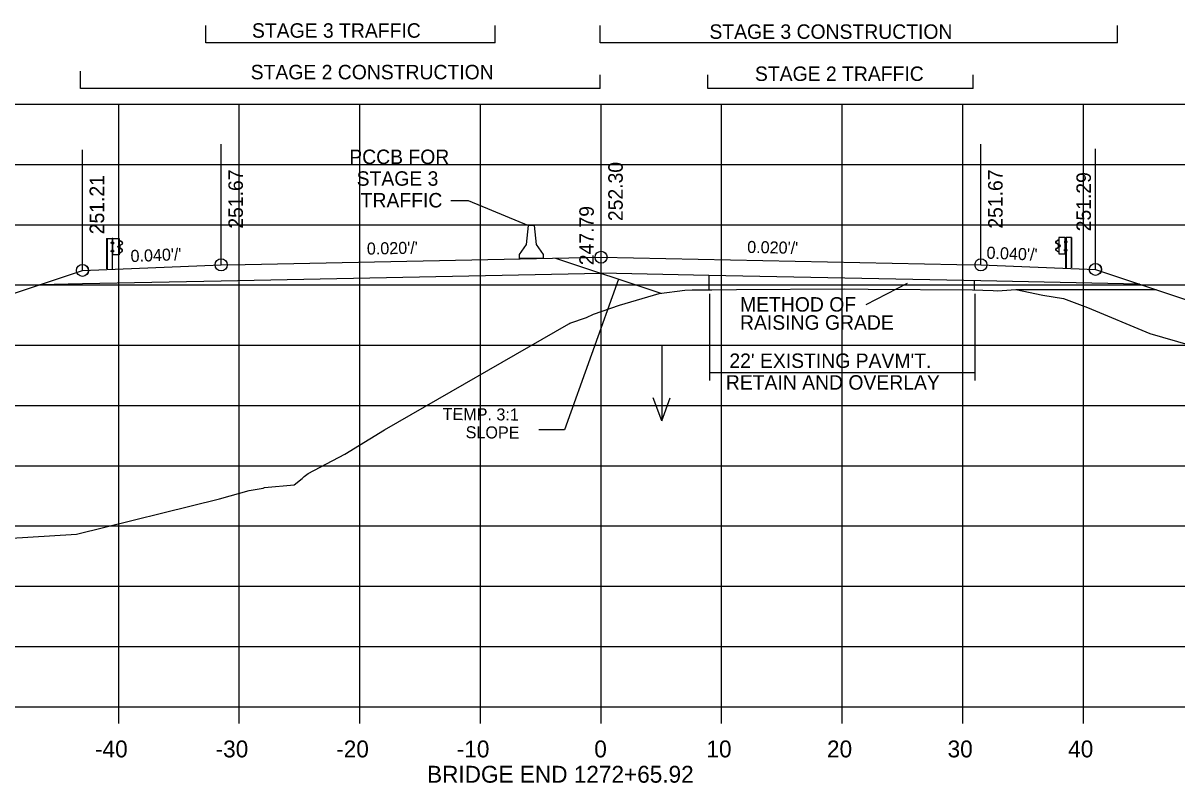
# Model space of a CAD drawing. Extents: x 1342547 to 1344156, y -1532351 to -1517216.
# Drawn here: x 1342654.9 to 1342750.6, y -1523508.6 to -1523445.5 of the extents above; entities that cross this region are included whole.
import ezdxf

# ---------------------------------------------------------------- set-up
doc = ezdxf.new("R2010")
doc.units = 0
for name, color, linetype in [('1', 7, 'Continuous'), ('R_Alt Surface', 7, 'Continuous'), ('R_Axis', 7, 'Continuous'), ('R_Axis Annot', 7, 'Continuous'), ('R_Draft', 7, 'Continuous'), ('R_Exist Surface', 7, 'Continuous'), ('R_Fin Surface', 7, 'Continuous'), ('R_Grid', 7, 'Continuous'), ('R_MOT', 7, 'Continuous'), ('R_No Plot', 7, 'Continuous'), ('R_Water', 7, 'Continuous'), ('R_Xsect Elev', 7, 'Continuous'), ('R_Xsect Slope', 7, 'Continuous')]:
    doc.layers.add(name, color=color, linetype=linetype)

msp = doc.modelspace()

# ---------------------------------------------------------------- linework, layer by layer
at = {"layer": '1'}
msp.add_lwpolyline([(1342743.866, -1523465.965), (1342803.434, -1523485.821)], dxfattribs=at)
at = {"layer": 'R_Alt Surface'}
msp.add_line((1342711.81, -1523466.467), (1342702.865, -1523466.288), dxfattribs=at)
for points in [[(1342659.865, -1523467.148), (1342671.365, -1523466.918), (1342702.865, -1523466.288)], [(1342747.514, -1523467.181), (1342734.365, -1523466.918), (1342711.81, -1523466.467)], [(1342656.338, -1523467.219), (1342659.865, -1523467.148)]]:
    msp.add_lwpolyline(points, dxfattribs=at)
at = {"layer": 'R_Axis'}
for p, q in [((1342562.865, -1523502.255), (1342842.865, -1523502.255)), ((1342662.865, -1523503.655), (1342662.865, -1523502.255)), ((1342672.865, -1523503.655), (1342672.865, -1523502.255)), ((1342682.865, -1523503.655), (1342682.865, -1523502.255)), ((1342692.865, -1523503.655), (1342692.865, -1523502.255)), ((1342702.865, -1523503.655), (1342702.865, -1523502.255)), ((1342712.865, -1523503.655), (1342712.865, -1523502.255)), ((1342722.865, -1523503.655), (1342722.865, -1523502.255)), ((1342732.865, -1523503.655), (1342732.865, -1523502.255)), ((1342742.865, -1523503.655), (1342742.865, -1523502.255))]:
    msp.add_line(p, q, dxfattribs=at)
at = {"layer": 'R_Draft'}
for p, q in [((1342670.098, -1523447.16), (1342670.098, -1523445.729)), ((1342694.098, -1523447.16), (1342694.098, -1523445.729)), ((1342702.783, -1523447.16), (1342702.783, -1523445.729)), ((1342745.702, -1523447.16), (1342745.702, -1523445.729)), ((1342694.098, -1523447.16), (1342670.098, -1523447.16)), ((1342745.702, -1523447.16), (1342702.783, -1523447.16)), ((1342659.692, -1523450.956), (1342659.692, -1523449.525)), ((1342702.783, -1523450.956), (1342702.783, -1523449.811)), ((1342711.721, -1523450.956), (1342711.721, -1523449.811)), ((1342733.723, -1523450.956), (1342733.723, -1523449.811)), ((1342702.783, -1523450.956), (1342659.692, -1523450.956)), ((1342733.723, -1523450.956), (1342711.721, -1523450.956)), ((1342661.867, -1523463.4), (1342661.867, -1523465.916)), ((1342661.897, -1523463.4), (1342661.897, -1523465.916)), ((1342662.267, -1523463.81), (1342662.267, -1523463.716)), ((1342662.322, -1523463.826), (1342662.272, -1523463.826)), ((1342662.322, -1523463.731), (1342662.273, -1523463.731)), ((1342662.322, -1523463.795), (1342662.273, -1523463.795)), ((1342662.322, -1523463.701), (1342662.274, -1523463.701)), ((1342662.322, -1523463.795), (1342662.279, -1523463.795)), ((1342662.322, -1523463.826), (1342662.322, -1523463.701)), ((1342662.392, -1523463.398), (1342662.323, -1523463.401)), ((1342662.358, -1523465.916), (1342662.358, -1523463.398)), ((1342662.392, -1523463.398), (1342662.386, -1523463.398)), ((1342662.447, -1523463.769), (1342662.391, -1523463.769)), ((1342662.398, -1523463.831), (1342662.448, -1523463.831)), ((1342662.399, -1523463.706), (1342662.448, -1523463.706)), ((1342662.448, -1523463.706), (1342662.448, -1523463.831)), ((1342662.823, -1523464.132), (1342662.823, -1523464.037)), ((1342662.878, -1523464.147), (1342662.828, -1523464.147)), ((1342662.878, -1523464.053), (1342662.829, -1523464.053)), ((1342662.878, -1523464.117), (1342662.829, -1523464.117)), ((1342662.878, -1523464.022), (1342662.83, -1523464.022)), ((1342662.878, -1523464.117), (1342662.835, -1523464.117)), ((1342662.878, -1523464.147), (1342662.878, -1523464.022)), ((1342662.891, -1523464.766), (1342662.891, -1523463.406)), ((1342663.035, -1523463.614), (1342662.923, -1523463.554)), ((1342663.022, -1523463.63), (1342662.929, -1523463.58)), ((1342662.93, -1523464.146), (1342662.932, -1523464.015)), ((1342662.954, -1523464.147), (1342662.956, -1523464.015)), ((1342662.977, -1523463.946), (1342663.149, -1523463.841)), ((1342663.139, -1523464.298), (1342662.985, -1523464.201)), ((1342662.99, -1523463.967), (1342663.162, -1523463.862)), ((1342663.152, -1523463.734), (1342663.022, -1523463.63)), ((1342663.165, -1523463.718), (1342663.035, -1523463.614)), ((1342740.588, -1523463.637), (1342740.718, -1523463.533)), ((1342740.763, -1523463.886), (1342740.591, -1523463.781)), ((1342740.601, -1523463.653), (1342740.731, -1523463.549)), ((1342740.776, -1523463.865), (1342740.604, -1523463.76)), ((1342740.614, -1523464.217), (1342740.768, -1523464.12)), ((1342740.626, -1523464.237), (1342740.781, -1523464.14)), ((1342740.718, -1523463.533), (1342740.83, -1523463.473)), ((1342740.731, -1523463.549), (1342740.824, -1523463.499)), ((1342740.799, -1523464.066), (1342740.797, -1523463.934)), ((1342740.823, -1523464.065), (1342740.821, -1523463.934)), ((1342740.862, -1523464.685), (1342740.862, -1523463.325)), ((1342740.875, -1523464.066), (1342740.875, -1523463.941)), ((1342740.875, -1523463.941), (1342740.923, -1523463.941)), ((1342740.875, -1523463.972), (1342740.924, -1523463.972)), ((1342740.875, -1523464.036), (1342740.918, -1523464.036)), ((1342740.875, -1523464.036), (1342740.924, -1523464.036)), ((1342740.875, -1523464.066), (1342740.925, -1523464.066)), ((1342740.93, -1523464.051), (1342740.93, -1523463.956)), ((1342741.354, -1523463.625), (1342741.305, -1523463.625)), ((1342741.305, -1523463.625), (1342741.305, -1523463.75)), ((1342741.355, -1523463.75), (1342741.305, -1523463.75)), ((1342741.306, -1523463.688), (1342741.362, -1523463.688)), ((1342741.361, -1523463.317), (1342741.367, -1523463.317)), ((1342741.361, -1523463.317), (1342741.43, -1523463.32)), ((1342741.395, -1523465.834), (1342741.395, -1523463.317)), ((1342741.431, -1523463.745), (1342741.431, -1523463.62)), ((1342741.431, -1523463.62), (1342741.479, -1523463.62)), ((1342741.431, -1523463.65), (1342741.48, -1523463.65)), ((1342741.431, -1523463.714), (1342741.474, -1523463.714)), ((1342741.431, -1523463.714), (1342741.48, -1523463.714)), ((1342741.431, -1523463.745), (1342741.481, -1523463.745)), ((1342741.486, -1523463.729), (1342741.486, -1523463.635)), ((1342741.856, -1523463.319), (1342741.856, -1523465.834)), ((1342741.886, -1523463.319), (1342741.886, -1523465.834)), ((1342662.257, -1523464.5), (1342662.257, -1523464.405)), ((1342662.312, -1523464.421), (1342662.262, -1523464.421)), ((1342662.312, -1523464.485), (1342662.262, -1523464.485)), ((1342662.312, -1523464.515), (1342662.262, -1523464.515)), ((1342662.312, -1523464.39), (1342662.263, -1523464.39)), ((1342662.312, -1523464.485), (1342662.269, -1523464.485)), ((1342662.312, -1523464.515), (1342662.312, -1523464.39)), ((1342662.391, -1523464.766), (1342662.357, -1523464.766)), ((1342662.447, -1523464.453), (1342662.391, -1523464.453)), ((1342662.448, -1523464.515), (1342662.398, -1523464.515)), ((1342662.448, -1523464.39), (1342662.399, -1523464.39)), ((1342662.448, -1523464.515), (1342662.448, -1523464.39)), ((1342662.919, -1523464.604), (1342663.027, -1523464.549)), ((1342662.927, -1523464.623), (1342663.041, -1523464.565)), ((1342663.127, -1523464.318), (1342662.972, -1523464.221)), ((1342663.027, -1523464.549), (1342663.153, -1523464.44)), ((1342663.041, -1523464.565), (1342663.167, -1523464.456)), ((1342699.091, -1523465.03), (1342707.819, -1523467.94)), ((1342740.712, -1523464.484), (1342740.586, -1523464.375)), ((1342740.726, -1523464.468), (1342740.6, -1523464.359)), ((1342740.826, -1523464.542), (1342740.712, -1523464.484)), ((1342740.834, -1523464.523), (1342740.726, -1523464.468)), ((1342741.305, -1523464.434), (1342741.305, -1523464.309)), ((1342741.305, -1523464.309), (1342741.354, -1523464.309)), ((1342741.305, -1523464.434), (1342741.355, -1523464.434)), ((1342741.306, -1523464.372), (1342741.362, -1523464.372)), ((1342741.362, -1523464.685), (1342741.396, -1523464.685)), ((1342741.441, -1523464.434), (1342741.441, -1523464.309)), ((1342741.441, -1523464.309), (1342741.49, -1523464.309)), ((1342741.441, -1523464.34), (1342741.491, -1523464.34)), ((1342741.441, -1523464.404), (1342741.484, -1523464.404)), ((1342741.441, -1523464.404), (1342741.491, -1523464.404)), ((1342741.441, -1523464.434), (1342741.491, -1523464.434)), ((1342741.496, -1523464.419), (1342741.496, -1523464.324)), ((1342711.81, -1523466.467), (1342711.81, -1523467.638)), ((1342733.811, -1523466.907), (1342733.811, -1523467.659)), ((1342711.866, -1523467.983), (1342711.866, -1523475.181)), ((1342733.868, -1523467.983), (1342733.868, -1523475.181)), ((1342711.866, -1523474.508), (1342733.868, -1523474.508))]:
    msp.add_line(p, q, dxfattribs=at)
for points in [[(1342690.397, -1523460.236), (1342691.838, -1523460.236)], [(1342691.838, -1523460.236), (1342696.84, -1523462.32)], [(1342661.867, -1523463.4), (1342662.323, -1523463.401), (1342662.322, -1523465.916)], [(1342741.886, -1523463.319), (1342741.43, -1523463.32), (1342741.431, -1523465.834)]]:
    msp.add_lwpolyline(points, dxfattribs=at)
for points in [[(1342662.265, -1523463.732), (1342662.265, -1523463.794), (1342662.24, -1523463.794), (1342662.24, -1523463.732)], [(1342662.321, -1523463.681), (1342662.321, -1523463.849), (1342662.331, -1523463.849), (1342662.331, -1523463.681)], [(1342662.917, -1523463.399), (1342662.916, -1523464.766), (1342662.391, -1523464.766), (1342662.392, -1523463.398)], [(1342662.447, -1523463.706), (1342662.447, -1523463.831), (1342662.392, -1523463.831), (1342662.392, -1523463.706)], [(1342662.821, -1523464.053), (1342662.821, -1523464.116), (1342662.796, -1523464.116), (1342662.796, -1523464.053)], [(1342662.877, -1523464.002), (1342662.877, -1523464.17), (1342662.887, -1523464.17), (1342662.887, -1523464.002)], [(1342740.836, -1523463.318), (1342740.837, -1523464.685), (1342741.362, -1523464.685), (1342741.361, -1523463.317)], [(1342740.876, -1523463.921), (1342740.876, -1523464.089), (1342740.866, -1523464.089), (1342740.866, -1523463.921)], [(1342740.932, -1523463.972), (1342740.932, -1523464.035), (1342740.957, -1523464.035), (1342740.957, -1523463.972)], [(1342741.306, -1523463.625), (1342741.306, -1523463.75), (1342741.361, -1523463.75), (1342741.361, -1523463.625)], [(1342741.432, -1523463.6), (1342741.432, -1523463.768), (1342741.422, -1523463.768), (1342741.422, -1523463.6)], [(1342741.488, -1523463.651), (1342741.488, -1523463.713), (1342741.513, -1523463.713), (1342741.513, -1523463.651)], [(1342662.254, -1523464.421), (1342662.254, -1523464.484), (1342662.229, -1523464.484), (1342662.229, -1523464.421)], [(1342662.31, -1523464.37), (1342662.31, -1523464.538), (1342662.32, -1523464.538), (1342662.32, -1523464.37)], [(1342662.447, -1523464.39), (1342662.447, -1523464.515), (1342662.392, -1523464.515), (1342662.392, -1523464.39)], [(1342741.306, -1523464.309), (1342741.306, -1523464.434), (1342741.361, -1523464.434), (1342741.361, -1523464.309)], [(1342741.443, -1523464.289), (1342741.443, -1523464.457), (1342741.433, -1523464.457), (1342741.433, -1523464.289)], [(1342741.499, -1523464.34), (1342741.499, -1523464.403), (1342741.524, -1523464.403), (1342741.524, -1523464.34)]]:
    msp.add_lwpolyline(points, close=True, dxfattribs=at)
for centre, radius, start, end in [((1342662.289, -1523463.717), 0.022, 134.57445, 222.22441), ((1342662.36, -1523463.764), 0.0922, 159.74227, 200.25773), ((1342662.293, -1523463.811), 0.025, 140.93341, 216.62337), ((1342662.845, -1523464.038), 0.022, 134.57445, 222.22441), ((1342662.916, -1523464.085), 0.0922, 159.74227, 200.25773), ((1342662.849, -1523464.133), 0.025, 140.93341, 216.62337), ((1342663, -1523464.157), 0.0703, 171.78044, 246.85364), ((1342663.018, -1523464.023), 0.0865, 118.10599, 175.04439), ((1342662.949, -1523464.09), 0.0453, 282.95537, 86.06973), ((1342663, -1523464.157), 0.0462, 171.78044, 246.85364), ((1342663.018, -1523464.023), 0.0622, 118.10599, 175.04439), ((1342663.119, -1523463.787), 0.062, 299.24991, 57.97825), ((1342663.119, -1523463.787), 0.0856, 299.24991, 57.97825), ((1342740.634, -1523463.706), 0.0856, 122.02175, 240.75009), ((1342740.634, -1523463.706), 0.062, 122.02175, 240.75009), ((1342740.804, -1523464.008), 0.0453, 93.93027, 257.04463), ((1342740.735, -1523463.941), 0.0622, 4.95561, 61.89401), ((1342740.753, -1523464.075), 0.0462, 293.14636, 8.21956), ((1342740.735, -1523463.941), 0.0865, 4.95561, 61.89401), ((1342740.753, -1523464.075), 0.0703, 293.14636, 8.21956), ((1342740.907, -1523463.957), 0.022, 317.77559, 45.42555), ((1342740.837, -1523464.003), 0.0922, 339.74227, 20.25773), ((1342740.904, -1523464.051), 0.025, 323.37663, 39.06659), ((1342741.463, -1523463.635), 0.022, 317.77559, 45.42555), ((1342741.393, -1523463.682), 0.0922, 339.74227, 20.25773), ((1342741.46, -1523463.73), 0.025, 323.37663, 39.06659), ((1342662.279, -1523464.406), 0.022, 134.57445, 222.22441), ((1342662.349, -1523464.453), 0.0922, 159.74227, 200.25773), ((1342662.282, -1523464.501), 0.025, 140.93341, 216.62337), ((1342663.083, -1523464.392), 0.0854, 325.21842, 59.11995), ((1342663.083, -1523464.392), 0.109, 325.21843, 59.11995), ((1342740.67, -1523464.31), 0.109, 120.88005, 214.78158), ((1342740.67, -1523464.31), 0.0854, 120.88005, 214.78158), ((1342741.474, -1523464.325), 0.022, 317.77559, 45.42555), ((1342741.404, -1523464.371), 0.0922, 339.74227, 20.25773), ((1342741.471, -1523464.419), 0.025, 323.37663, 39.06659)]:
    msp.add_arc(centre, radius, start, end, dxfattribs=at)
at = {"layer": 'R_Exist Surface'}
msp.add_lwpolyline([(1342640.044, -1523489.129), (1342659.37, -1523487.943), (1342671.227, -1523485.013), (1342673.695, -1523484.315), (1342674.835, -1523484.111), (1342674.97, -1523484.055), (1342677.422, -1523483.842), (1342678.093, -1523483.327), (1342678.257, -1523483.161), (1342678.565, -1523482.91), (1342681.628, -1523481.282), (1342684.922, -1523479.279), (1342700.197, -1523470.47), (1342700.285, -1523470.428), (1342701.655, -1523469.951), (1342702.228, -1523469.68), (1342704.404, -1523468.939), (1342707.673, -1523467.958), (1342709.825, -1523467.69), (1342710.413, -1523467.657), (1342712.05, -1523467.652), (1342714.09, -1523467.63), (1342723.037, -1523467.573), (1342725.004, -1523467.595), (1342733.659, -1523467.659), (1342735.393, -1523467.727), (1342735.769, -1523467.741), (1342736.863, -1523467.672), (1342737.265, -1523467.645), (1342739.49, -1523468.092), (1342741.212, -1523468.369), (1342743.213, -1523469.136), (1342748.383, -1523471.286), (1342751.715, -1523472.256)], dxfattribs=at)
at = {"layer": 'R_Fin Surface'}
for points in [[(1342590.328, -1523489.222), (1342659.855, -1523466.047), (1342659.865, -1523466.045), (1342671.365, -1523465.585), (1342673.365, -1523465.545), (1342702.865, -1523464.955), (1342732.365, -1523465.545), (1342734.365, -1523465.585), (1342743.866, -1523465.965)], [(1342737.265, -1523467.645), (1342748.905, -1523467.645)]]:
    msp.add_lwpolyline(points, dxfattribs=at)
at = {"layer": 'R_Grid'}
for p, q in [((1342562.865, -1523452.255), (1342842.865, -1523452.255)), ((1342662.865, -1523502.255), (1342662.865, -1523452.255)), ((1342672.865, -1523502.255), (1342672.865, -1523452.255)), ((1342682.865, -1523502.255), (1342682.865, -1523452.255)), ((1342692.865, -1523502.255), (1342692.865, -1523452.255)), ((1342702.865, -1523502.255), (1342702.865, -1523452.255)), ((1342712.865, -1523502.255), (1342712.865, -1523452.255)), ((1342722.865, -1523502.255), (1342722.865, -1523452.255)), ((1342732.865, -1523502.255), (1342732.865, -1523452.255)), ((1342742.865, -1523502.255), (1342742.865, -1523452.255)), ((1342562.865, -1523457.255), (1342842.865, -1523457.255)), ((1342562.865, -1523462.255), (1342842.865, -1523462.255)), ((1342562.865, -1523467.255), (1342842.865, -1523467.255)), ((1342562.865, -1523472.255), (1342842.865, -1523472.255)), ((1342562.865, -1523477.255), (1342842.865, -1523477.255)), ((1342562.865, -1523482.255), (1342842.865, -1523482.255)), ((1342562.865, -1523487.255), (1342842.865, -1523487.255)), ((1342562.865, -1523492.255), (1342842.865, -1523492.255)), ((1342562.865, -1523497.255), (1342842.865, -1523497.255)), ((1342562.865, -1523502.255), (1342842.865, -1523502.255))]:
    msp.add_line(p, q, dxfattribs=at)
at = {"layer": 'R_MOT'}
for p, q in [((1342696.673, -1523463.903), (1342696.84, -1523462.32)), ((1342697.09, -1523462.32), (1342696.84, -1523462.32)), ((1342697.34, -1523462.32), (1342697.09, -1523462.32)), ((1342697.508, -1523463.903), (1342697.34, -1523462.32)), ((1342696.098, -1523464.736), (1342696.673, -1523463.903)), ((1342698.098, -1523464.736), (1342697.508, -1523463.903)), ((1342696.091, -1523465.069), (1342696.098, -1523464.736)), ((1342698.091, -1523465.069), (1342696.091, -1523465.069)), ((1342698.091, -1523465.069), (1342698.098, -1523464.736))]:
    msp.add_line(p, q, dxfattribs=at)
at = {"layer": 'R_No Plot'}
for centre in [(1342671.365, -1523465.585), (1342702.865, -1523464.955), (1342734.365, -1523465.585), (1342659.855, -1523466.047), (1342659.865, -1523466.045), (1342743.856, -1523465.963), (1342743.866, -1523465.965)]:
    msp.add_circle(centre, 0.5, dxfattribs=at)
at = {"layer": 'R_Water'}
for p, q in [((1342707.9, -1523472.248), (1342707.9, -1523478.533)), ((1342707.9, -1523478.533), (1342707.2, -1523476.609)), ((1342707.9, -1523478.533), (1342708.6, -1523476.609))]:
    msp.add_line(p, q, dxfattribs=at)
at = {"layer": 'R_Xsect Elev'}
for p, q in [((1342671.365, -1523465.585), (1342671.365, -1523455.585)), ((1342702.865, -1523464.955), (1342702.865, -1523454.955)), ((1342734.365, -1523465.585), (1342734.365, -1523455.585)), ((1342659.855, -1523466.047), (1342659.855, -1523456.047)), ((1342659.865, -1523466.045), (1342659.865, -1523456.045)), ((1342743.856, -1523465.963), (1342743.856, -1523455.963)), ((1342743.866, -1523465.965), (1342743.866, -1523455.965)), ((1342702.865, -1523469.463), (1342702.865, -1523459.463)), ((1342704.307, -1523466.769), (1342699.839, -1523479.266)), ((1342728.257, -1523467.136), (1342724.834, -1523468.897)), ((1342699.839, -1523479.266), (1342697.698, -1523479.266))]:
    msp.add_line(p, q, dxfattribs=at)

# ---------------------------------------------------------------- texts
at = {"layer": 'R_Axis Annot'}
for s, p in [('-40', (1342660.904, -1523506.455)), ('-30', (1342670.904, -1523506.455)), ('-20', (1342680.904, -1523506.455)), ('-10', (1342690.904, -1523506.455)), ('0', (1342702.304, -1523506.455)), ('10', (1342711.604, -1523506.455)), ('20', (1342721.604, -1523506.455)), ('30', (1342731.604, -1523506.455)), ('40', (1342741.604, -1523506.455)), ('BRIDGE END 1272+65.92', (1342688.435, -1523508.555))]:
    msp.add_text(s, height=1.4, dxfattribs=at).set_placement(p)
at = {"layer": 'R_Draft'}
for s, p in [('STAGE 3 TRAFFIC', (1342673.917, -1523446.743)), ('STAGE 3 CONSTRUCTION', (1342711.853, -1523446.834)), ('STAGE 2 CONSTRUCTION', (1342673.812, -1523450.193)), ('STAGE 2 TRAFFIC', (1342715.627, -1523450.329)), ('PCCB FOR', (1342681.987, -1523457.225)), ('STAGE 3', (1342682.597, -1523459.025)), ('TRAFFIC', (1342682.932, -1523460.825)), ("22' EXISTING PAVM'T.", (1342713.507, -1523474.143)), ('RETAIN AND OVERLAY', (1342713.214, -1523475.943))]:
    msp.add_text(s, height=1.2, dxfattribs=at).set_placement(p)
at = {"layer": 'R_Xsect Elev'}
for s, p in [('252.30', (1342704.665, -1523461.955)), ('251.21', (1342661.655, -1523463.047)), ('251.21', (1342661.665, -1523463.045)), ('251.67', (1342673.165, -1523462.585)), ('251.67', (1342736.165, -1523462.585)), ('251.29', (1342743.485, -1523462.806)), ('247.79', (1342702.265, -1523465.615))]:
    msp.add_text(s, height=1.2, rotation=90, dxfattribs=at).set_placement(p)
for s, p in [('METHOD OF ', (1342714.39, -1523469.468)), ('RAISING GRADE', (1342714.39, -1523470.97))]:
    msp.add_text(s, height=1.2, dxfattribs=at).set_placement(p)
at = {"layer": 'R_Xsect Slope'}
for s, rotation, p in [("0.040'/'", 2.29061, (1342663.868, -1523465.361)), ("0.020'/'", 1.14576, (1342683.454, -1523464.743)), ("0.020'/'", 358.85424, (1342714.978, -1523464.597)), ("0.040'/'", 357.70839, (1342734.814, -1523465.07)), ('TEMP. 3:1', 359.62418, (1342689.727, -1523478.464)), ('SLOPE', 359.62418, (1342691.637, -1523479.977))]:
    msp.add_text(s, height=1, rotation=rotation, dxfattribs=at).set_placement(p)

doc.saveas('drawing.dxf')
